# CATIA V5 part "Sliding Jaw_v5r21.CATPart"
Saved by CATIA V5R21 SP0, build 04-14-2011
Part number: Sliding Jaw
Bounding box of the stored display mesh (mm): x -32 to 32, y -16 to 16, z -9 to 36
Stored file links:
  D:\CATIA V5R21 E-RESOURCES\CATIA-V5R21\catia-v5r21-Tut\c13-catia-v5r21-tut\c13-catia-v5r21-tut02\Bench Vice\Sliding Jaw_v5r21.CATPart
  C:\Program Files\Dassault Systemes\B09\intel_a\reffiles\standard\MetricThickPitch.txt
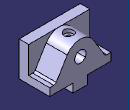
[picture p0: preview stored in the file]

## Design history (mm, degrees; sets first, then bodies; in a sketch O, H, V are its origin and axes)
Body1 (main body)
  Sketch1 on xy-plane, origin (0, 0, 0), H (1, 0, 0), V (0, 1, 0)
    line L1 (-32, -16) -> (32, -16)
    line L2 (32, -16) -> (32, 16)
    line L3 (32, 16) -> (-32, 16)
    line L4 (-32, 16) -> (-32, -16)
    distance H L1 = 16
    distance V L4 = 32
    length L4 = 32
    length L1 = 64
    horizontal: L1 H, L3 H
    vertical: L2 V, L4 V
  Pad1: profile Sketch1, direction (0, 0, 1), length 8
  Sketch2 on face of Pad1, origin (0, -16, 0), H (1, 0, 0), V (0, 0, 1)
    point P1 (-32, 0)
    line L1 (-32, 0) -> (32, 0)
    line L2 (32, 0) -> (32, 36)
    line L3 (32, 36) -> (-32, 36)
    line L4 (-32, 36) -> (-32, 0)
    reference projected line E1 (32, 0) -> (32, 8) from edge of Pad1
    reference projected line E2 (-32, 8) -> (-32, 0) from edge of Pad1
    length L2 = 36
    coincidence: P1 H, L2 E1, L4 E2
    horizontal: L1 H, L3 H
    vertical: L2 V, L4 V
  Pad2: profile Sketch2, direction (0, 1, 0), length 10
  Sketch3 on face of Pad1, origin (0, 16, 0), H (-1, 0, 0), V (0, 0, 1)
    arc A1 centre (0, 20) radius 16 from (13.6777, 28.3018) to (-13.6777, 28.3018) ccw
    point P1 (0, 20)
    reference projected line E1 (-32, 36) -> (32, 36) from edge of Pad2
    line L1 (-26, 8) -> (-13.6777, 28.3018)
    point P2 (-26, 8)
    line L2 (13.6777, 28.3018) -> (26, 8)
    point P3 (26, 8)
    reference projected line E2 (32, 8) -> (-32, 8) from edge of Pad1
    reference projected line E3 (32, 8) -> (-32, 8) from edge of Pad1
    line L3 (-26, 8) -> (26, 8)
    radius A1 = 16
    length L3 = 52
    distance V P3 = 26
    coincidence: P1 V, E2 P2, E3 P3
    tangency: A1 E1, L2 A1, L1 A1
    horizontal: L3 H
  Pad3: profile Sketch3, direction (0, -1, 0), up to the existing solid (limit type 2)
  Fillet1: radius 3, on 2 edges
  Sketch4 on face of Pad1, origin (-2.6964, 16, 22.8197), H (1, 0, 0), V (0, 0, -1)
    point P1 (2.6964, 2.8197)
    reference projected arc E1 centre (2.6964, 2.8197) radius 16 from (-10.9814, -5.4821) to (16.3741, -5.4821) ccw from edge of Pad3
    concentricity: P1 E1
  Hole1: placed by Sketch4, at (0, 16, 20) direction (0, -1, 0), diameter 12, depth 22, V-bottom angle 120
  Sketch5 on face of Pad1, origin (0, 16, 0), H (-1, 0, 0), V (0, 0, 1)
    point P1 (-7.75, 0)
    line L1 (-7.75, 0) -> (7.75, 0)
    line L2 (7.75, 0) -> (7.75, -9)
    line L3 (7.75, -9) -> (-7.75, -9)
    line L4 (-7.75, -9) -> (-7.75, 0)
    distance V L2 = 7.75
    length L3 = 15.5
    length L4 = 9
    coincidence: P1 H
    horizontal: L1 H, L3 H
    vertical: L2 V, L4 V
  Pad4: profile Sketch5, direction (0, -1, 0), length 32
  Sketch6 on face of Pad4, origin (-0.598, -1.2346, -9), H (1, 0, 0), V (0, -1, 0)
    point P1 (0.598, -9.2346)
    reference projected line E1 (8.348, -17.2346) -> (-7.152, -17.2346) from edge of Pad4
    reference projected line E2 (8.348, 14.7654) -> (8.348, -17.2346) from edge of Pad4
    distance P1 E1 = 8
    distance P1 E2 = 7.75
  Hole2: placed by Sketch6, at (0, 8, -9) direction (0, 0, 1), diameter 5, depth 16, V-bottom angle 120, threaded, thread diameter 6, thread depth 16, pitch 1
  RectPattern1: of Hole2, direction 1 instances 2, spacing 16, along edge of Pad4 reversed
  Sketch7 on face of Pad2, origin (-19.6018, -13.7351, 36), H (1, 0, 0), V (0, 1, 0)
    point P1 (19.6018, 17.7351)
    reference intersected line E1 through (19.6018, 0) direction (0, 1) from yz-plane
    reference projected line E2 (51.6018, -2.2649) -> (-12.3982, -2.2649) from edge of Pad2
    distance P1 E2 = 20
    coincidence: E1 P1
  Hole3: placed by Sketch7, at (0, 4, 36) direction (0, 0, -1), diameter 5, depth 16, V-bottom angle 120, counterbore diameter 10, counterbore depth 4, threaded, thread diameter 6, thread depth 11, pitch 1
